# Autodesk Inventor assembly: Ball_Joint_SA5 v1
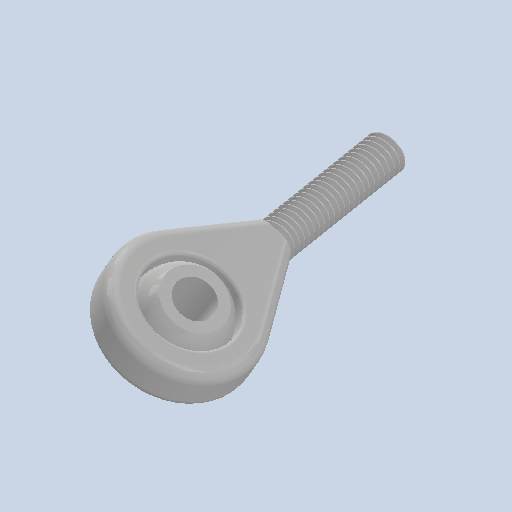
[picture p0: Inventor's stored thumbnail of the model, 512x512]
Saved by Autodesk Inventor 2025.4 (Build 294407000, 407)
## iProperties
Created: 2026-09
Part Number: Ball_Joint_SA5 v1
Document SubType Name: Assembly
Designer: AdminForWorker
Title: rotula v1
Author: AdminForWorker
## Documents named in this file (3)
- c:\worker\convert-fusion-r05-cosv3\tmp\job-1\19\temp\files\ca3d996b-dda0-445d-8bee-12a194174ca8\rotula v1.iam
- c:\worker\convert-fusion-r05-cosv3\tmp\job-1\19\temp\files\ca3d996b-dda0-445d-8bee-12a194174ca8\Component33.ipt
- c:\worker\convert-fusion-r05-cosv3\tmp\job-1\19\temp\files\ca3d996b-dda0-445d-8bee-12a194174ca8\Component34.ipt
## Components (2 placed, 2 different names)
1. Component33:1
2. Component34:1
